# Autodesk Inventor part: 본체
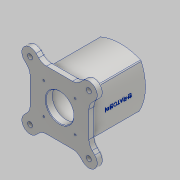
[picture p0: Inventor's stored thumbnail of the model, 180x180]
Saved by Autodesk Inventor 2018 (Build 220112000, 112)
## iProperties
Created: 2022-01
Part Number: 본체
Material: 알루미늄 6061
Document SubType Name: Modeling
Designer: home
Density: 2.7 g/cm^3
Appearance: 알루미늄 - 평지
Mass: 1226.53 g
Surface Area: 908.487 cm^2
Volume: 454.27 cm^3
Author: home
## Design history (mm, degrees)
sketch "스케치1"
  geometry: L1 (32.942, -45)-(-32.942, -45); L2 (45, -45)-(-45, 45); L3 (-45, -45)-(45, 45); L4 (0, 0)-(0, -55.815); A1 r 90 centre (-45, 0) between (32.942, -45) and (37.029, 37.029); A2 r 90 centre (45, 0) between (-37.029, 37.029) and (-32.942, -45); A3 r 90 centre (0, -45) between (37.029, 37.029) and (-37.029, 37.029); 2 further points
  constraints: 8 end point, 7 point on circle, 3 centre point, 3 symmetric about line, 2 point on line, 1 equal radius, 1 horizontal, 1 midpoint, 1 perpendicular, 1 vertical, 1 other
  dimensions: "d2" = 90 distance of L2.end L3.end; "d3" = 90 distance of L3.start L2.end; "d4" = 180 diameter of A1; "d5" = 135 deg angle of L2 L4; "d6" = 0 distance from line of L4.start L2; "d7" = 0 distance from line of L4.start L3; "d8" = 45 distance from line of L4.start L1; "d9" = 63.63961 distance from line of L3.end L2; "d10" = 63.63961 distance from line of L2.start L3; "d11" = 55.11352 distance from line of point (32.942, 45) L2; "d12" = 8.52609 distance from line of point (32.942, 45) L3; "d13" = 39.4673 distance from line of L4.end L2
extrude "돌출1" new body sketch "스케치1" stored distance "d14" = 110; taper "d15" = 0 deg
sketch "스케치2"
  geometry: L1 (0, 0)-(0, -106.241); L2 (0, 0)-(85.273, -85.273); L3 (42.426, -63.64)-(31.787, -53); L4 (-31.787, 53)-(31.787, 53); L5 (53, 31.787)-(53, -31.787); L6 (-53, -31.787)-(-53, 31.787); L7 (-53, 53)-(53, -53); L8 (53, 53)-(-53, -53); L9 (31.787, -53)-(-31.787, -53); L10 (63.64, -42.426)-(53, -31.787); L11 (42.426, 63.64)-(31.787, 53); L12 (63.64, 42.426)-(53, 31.787); L13 (-63.64, 42.426)-(-53, 31.787); L14 (-42.426, 63.64)-(-31.787, 53); L15 (-42.426, -63.64)-(-31.787, -53); L16 (-63.64, -42.426)-(-53, -31.787); L17 (-32.942, -45)-(32.942, -45) reference; A1 r 75 centre (0, 0) between (53.033, -53.033) and (41.355, -62.568); A2 r 15 centre (53.033, -53.033) between (41.419, -62.526) and (62.526, -41.419); A3 r 15 centre (53.033, 53.033) between (62.526, 41.419) and (41.419, 62.526); A4 r 15 centre (-53.033, 53.033) between (-41.419, 62.526) and (-62.526, 41.419); A5 r 15 centre (-53.033, -53.033) between (-62.526, -41.419) and (-41.419, -62.526); A6 r 90 centre (-45, 0) between (32.942, -45) and (37.029, 37.029) reference; A7 r 90 centre (0, -45) between (37.029, 37.029) and (-37.029, 37.029) reference; A8 r 90 centre (45, 0) between (-37.029, 37.029) and (-32.942, -45) reference; 10 further points
  constraints: 32 end point, 20 point on circle, 9 point on line, 9 tangent, 6 parallel, 5 centre point, 2 midpoint, 2 perpendicular, 2 symmetric about line, 1 coincident, 1 equal radius, 1 horizontal, 1 vertical
  dimensions: "d39" = 150 diameter of A1; "d40" = 45 deg angle of L2 L1; "d41" = 30 diameter of A2; "d42" = 15 distance between parallel lines of L2 L3; "d44" = 106 distance of L8.start L7.end; "d45" = 53 distance from line of L5 point (0, 0); "d46" = 106 distance between parallel lines of L6 L5; "d47" = 53 distance from line of point (0, 0) L9; "d48" = 42.87983 distance from line of point (95.88, -74.667) L5; "d49" = 32.27323 distance from line of L2.end L5; "d50" = 90.12402 distance from line of L1.end L10; "d54" = 53 distance from line of point (0, 0) L4; "d55" = 90 deg angle of L12 L10; "d56" = 90 deg angle of L16 L10; "d57" = 90 deg angle of L12 L7; "d58" = 15 distance between parallel lines of L8 L11; "d59" = 15 distance from line of point (0, 0) L12; "d60" = 15 distance from line of point (0, 0) L16; "d61" = 0 distance from line of point (95.88, -74.667) L10; "d62" = 60 distance from line of L12.start L10; "d63" = 58.48469 distance from line of point (62.568, 41.355) L10; "d64" = 58.5 distance from line of A3.start L10; "d65" = 59.95332 distance from line of L8.start L10; "d66" = 58.5 distance from line of A3.end L10; "d67" = 58.48469 distance from line of point (41.355, 62.568) L10; "d68" = 88.48469 distance from line of point (-41.355, 62.568) L12; "d69" = 88.48469 distance from line of point (-41.355, -62.568) L10; "d70" = 0.07519 distance from line of A4.start L10; "d71" = 88.5 distance from line of A4.start L12; "d72" = 88.5 distance from line of A5.end L10; "d73" = 0.07519 distance from line of A5.end L12; "d74" = 89.95332 distance from line of L7.start L12; "d75" = 89.95332 distance from line of L8.end L10; "d76" = 29.92481 distance from line of A4.end L10; "d77" = 88.5 distance from line of A5.start L10; "d78" = 88.48469 distance from line of point (-62.568, 41.355) L12; "d79" = 88.48469 distance from line of point (-62.568, -41.355) L10
extrude "돌출2" join sketch "스케치2" distance "d80" = 12; taper "d81" = 0 deg
sketch "스케치3"
  geometry: C1 r 25 at (0, 0); 1 further point
  constraints: 1 centre point, 1 coincident
  dimensions: "d82" = 50 diameter of C1
extrude "돌출3" cut sketch "스케치3" distance "d83" = 12; taper "d84" = 0 deg
sketch "스케치4"
  geometry: C1 r 37 at (0, 0); 1 further point
  constraints: 1 centre point, 1 coincident
  dimensions: "d85" = 74 diameter of C1
extrude "돌출4" cut sketch "스케치4" distance "d86" = 86; taper "d87" = 0 deg
sketch "스케치5"
  geometry: C1 r 25 at (0, 0); 1 further point
  constraints: 1 centre point, 1 coincident
  dimensions: "d88" = 50 diameter of C1
extrude "돌출5" cut sketch "스케치5" distance "d89" = 12; taper "d90" = 0 deg
node "작업 평면1"
sketch "스케치6"
  geometry: L1 (-31.787, -55)-(31.787, -55) reference; C1 r 20 at (0, 6); 1 further point
  constraints: 1 centre point, 1 vertical alignment
  dimensions: "d92" = 40 diameter of C1; "d93" = 61 distance from line of C1.centre L1
extrude "돌출6" join sketch "스케치6" distance "d94" = 12; taper "d95" = 10 deg
sketch "스케치7"
  geometry: C1 r 20 at (0, 0) reference; C2 r 12 at (0, 0); 1 further point
  constraints: 1 centre point, 1 coincident
  dimensions: "d96" = 24 diameter of C2
extrude "돌출7" cut sketch "스케치7" distance "d97" = 13; taper "d98" = 0 deg
sketch "스케치8"
  geometry: C1 r 12 at (0, 0) reference; C2 r 15 at (0, 0); 1 further point
  constraints: 1 centre point, 1 coincident
  dimensions: "d99" = 30 diameter of C2
extrude "돌출8" cut sketch "스케치8" distance "d100" = 13; taper "d101" = 0 deg
sketch "스케치9"
  geometry: L1 (31.787, 53)-(42.426, 63.64) reference; L2 (63.64, 42.426)-(53, 31.787) reference; L3 (53, 31.787)-(53, -31.787) reference; L4 (53, -31.787)-(63.64, -42.426) reference; L5 (42.426, -63.64)-(31.787, -53) reference; L6 (31.787, -53)-(-31.787, -53) reference; L7 (-31.787, -53)-(-42.426, -63.64) reference; L8 (-63.64, -42.426)-(-53, -31.787) reference; L9 (-53, -31.787)-(-53, 31.787) reference; L10 (-53, 31.787)-(-63.64, 42.426) reference; L11 (-42.426, 63.64)-(-31.787, 53) reference; L12 (-31.787, 53)-(31.787, 53) reference; C1 r 25 at (0, 0) reference; C2 r 9 at (-53.033, 53.033); C3 r 9 at (-53.033, -53.033); C4 r 9 at (53.033, -53.033); C5 r 9 at (53.033, 53.033); A1 r 15 centre (53.033, 53.033) between (63.64, 42.426) and (42.426, 63.64) reference; A2 r 15 centre (53.033, -53.033) between (42.426, -63.64) and (63.64, -42.426) reference; A3 r 15 centre (-53.033, -53.033) between (-63.64, -42.426) and (-42.426, -63.64) reference; A4 r 15 centre (-53.033, 53.033) between (-42.426, 63.64) and (-63.64, 42.426) reference; 1 further point
  constraints: 4 centre point, 3 concentric, 3 equal radius, 1 coincident
  dimensions: "d102" = 18 diameter of C2
extrude "돌출9" cut sketch "스케치9" distance "d106" = 2; taper "d107" = 0 deg
sketch "스케치10"
  geometry: L1 (-21.246, -0.033)-(-10.607, 10.607) reference; L2 (10.607, -10.607)-(-0.033, -21.246) reference; L3 (-0.033, -21.246)-(-0.033, -84.82) reference; L4 (-0.033, -84.82)-(10.607, -95.459) reference; L5 (-10.607, -116.673)-(-21.246, -106.033) reference; L6 (-21.246, -106.033)-(-84.82, -106.033) reference; L7 (-84.82, -106.033)-(-95.459, -116.673) reference; L8 (-116.673, -95.459)-(-106.033, -84.82) reference; L9 (-106.033, -84.82)-(-106.033, -21.246) reference; L10 (-106.033, -21.246)-(-116.673, -10.607) reference; L11 (-95.459, 10.607)-(-84.82, -0.033) reference; L12 (-84.82, -0.033)-(-21.246, -0.033) reference; C1 r 25 at (-53.033, -53.033) reference; C2 r 4.5 at (-106.066, 0); C3 r 4.5 at (-106.066, -106.066); C4 r 4.5 at (0, -106.066); C5 r 4.5 at (0, 0); A1 r 15 centre (0, 0) between (10.607, -10.607) and (-10.607, 10.607) reference; A2 r 15 centre (0, -106.066) between (-10.607, -116.673) and (10.607, -95.459) reference; A3 r 15 centre (-106.066, -106.066) between (-116.673, -95.459) and (-95.459, -116.673) reference; A4 r 15 centre (-106.066, 0) between (-95.459, 10.607) and (-116.673, -10.607) reference; 1 further point
  constraints: 4 centre point, 3 concentric, 3 equal radius, 1 coincident
  dimensions: "d108" = 9 diameter of C2
extrude "돌출10" cut sketch "스케치10" distance "d112" = 10; taper "d113" = 0 deg
sketch "스케치11" dims "d114" = 80
  geometry: L1 (0, 0)-(0, 66.966); L2 (0, 0)-(-28.284, 28.284); 1 further point
  constraints: 4 end point, 1 coincident, 1 vertical, 3 other
  dimensions: "d115" = 45 deg angle of L1 L2
hole "구멍1" sketch "스케치11" at (-28.284, 28.284) diameter "d116" = 3.242; stored, may be unused: countersink angle "d120" = 90 deg, drill point angle "d122" = 118 deg; dims "d117" = 9, "d118" = 4, "d119" = 2, "d121" = 11
sketch "스케치12" dims "d126" = 80
  geometry: L1 (0, 0)-(-28.284, 28.284); L2 (0, 0)-(0, 64.675); 1 further point
  constraints: 4 end point, 1 coincident, 1 vertical, 3 other
  dimensions: "d127" = 45 deg angle of L2 L1
hole "구멍2" sketch "스케치12" at (-28.284, 28.284) diameter "d128" = 3.242; stored, may be unused: countersink angle "d132" = 90 deg, drill point angle "d134" = 118 deg; dims "d129" = 9, "d130" = 4, "d131" = 2, "d133" = 11
fillet "모깎기1" dims "d138" = 20
fillet "모깎기2" dims "d139" = 3
fillet "모깎기3" dims "d140" = 3
chamfer "모따기1" distance "d141" = 1; stored, may be unused: second distance "d142" = 2, angle "d143" = 45 deg
node "작업 평면2"
sketch "스케치13"
  geometry: L1 (-55, -23.503)-(-55, 23.503) reference; L2 (-14, -55)-(26, -55) reference; 2 further points
  constraints: 1 other
  dimensions: "d145" = 61 distance from line of point (6, 0) L1; "d146" = 55 distance from line of point (6, 0) L2
feature "엠보싱1" sketch "스케치13" dims "d39" = 150, "d40" = 45 deg, "d41" = 30, "d42" = 15, "d44" = 106, "d45" = 53, "d46" = 106, "d47" = 53, "d48" = 42.87983, "d49" = 32.27323, "d50" = 90.12402, "d54" = 53, "d55" = 90 deg, "d56" = 90 deg, "d57" = 90 deg, "d58" = 15, "d59" = 15, "d60" = 15, "d61" = 0 deg, "d62" = 60, "d63" = 58.48469, "d64" = 58.5, "d65" = 59.95332, "d66" = 58.5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
node "솔리드1"
pattern_circular "원형 패턴1" dims angle "d124" = 360 deg
pattern_circular "원형 패턴2" dims angle "d136" = 360 deg
node "투영된 루프1"
node "투영된 루프2"
node "투영된 루프3"
node "투영된 루프4"
node "투영된 루프5"
other parameters: "d91" = -55, "d144" = 45
